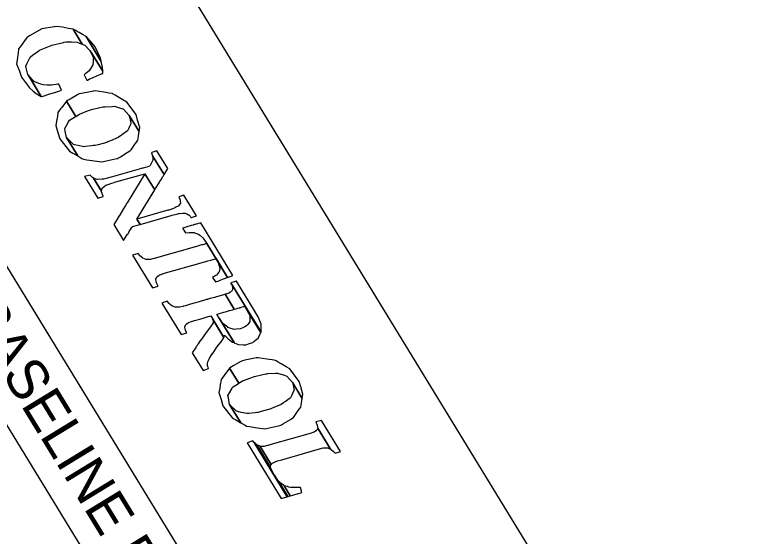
# Model space of a CAD drawing. Extents: x 1761551 to 1780507, y 798394 to 817574.
# Drawn here: x 1775599 to 1777513, y 809485 to 810828 of the extents above; entities that cross this region are included whole.
import ezdxf

# ---------------------------------------------------------------- set-up
doc = ezdxf.new("R2010")
doc.units = 0
for name, color, linetype in [('CTL Sheet Border CELL', 7, 'Continuous'), ('CTL Sheet Text', 7, 'Continuous'), ('Sheet Data Field CELL', 7, 'Continuous')]:
    doc.layers.add(name, color=color, linetype=linetype)

msp = doc.modelspace()

# ---------------------------------------------------------------- linework, layer by layer
at = {"layer": 'CTL Sheet Border CELL'}
for points in [[(1780191.8, 804106.2), (1772031, 817462.6), (1762681.6, 811750.1), (1770842.4, 798393.7)], [(1774358.1, 812175.1), (1777442.6, 807126.8), (1777261.6, 807016.3), (1774177.2, 812064.3)]]:
    msp.add_lwpolyline(points, close=True, dxfattribs=at)
at = {"layer": 'Sheet Data Field CELL'}
for points in [[(1775610.4, 810682.8), (1775616.1, 810667.3), (1775636.5, 810640.1), (1775646.1, 810631.8), (1775653.4, 810625.6), (1775666.6, 810617.7), (1775632.6, 810673.4), (1775632.3, 810674.6), (1775628.9, 810688.4), (1775627.1, 810695.9), (1775630.7, 810703.8), (1775633.6, 810710), (1775637.9, 810719.2), (1775645.3, 810724.7), (1775654.2, 810731.2), (1775654.2, 810731.3), (1775657.5, 810733.7), (1775661.8, 810736.8), (1775692, 810749.2), (1775692, 810749.2), (1775693.9, 810749.9), (1775724.1, 810757.1), (1775725.8, 810757.5), (1775730.7, 810758.6), (1775731.3, 810758.6), (1775744.7, 810758.3), (1775758.7, 810757.9), (1775765.3, 810755.2), (1775772.4, 810752.3), (1775748.8, 810791.1), (1775742.8, 810792.1), (1775737.2, 810793.1), (1775721.7, 810795.9), (1775707, 810798.4), (1775706.4, 810798.3), (1775701.4, 810797.4), (1775699.6, 810797.1), (1775668.3, 810791.7), (1775666.3, 810791.4), (1775638.4, 810775.1), (1775633.9, 810772.4), (1775630.4, 810770.3), (1775623.3, 810760.7), (1775617.5, 810752.6), (1775612.1, 810745.2), (1775608.4, 810740.2), (1775606.9, 810728.8), (1775606.4, 810725.2), (1775605.5, 810718.4), (1775605.5, 810717.8), (1775603.9, 810706.4), (1775603.3, 810701.9)], [(1775755.6, 810787.3), (1775748.8, 810791.1), (1775772.4, 810752.3), (1775778.5, 810749.9), (1775783.7, 810744.6), (1775784.4, 810743.9), (1775792.8, 810735.5), (1775824.8, 810683.1), (1775824.5, 810693.4), (1775821.3, 810708.2), (1775782, 810772.6), (1775773.1, 810777.5), (1775763.9, 810782.7), (1775759.1, 810785.3), (1775758.6, 810785.6)], [(1775793.1, 810759.9), (1775782, 810772.6), (1775821.3, 810708.2), (1775819.5, 810716.6), (1775805.7, 810745.4), (1775805.7, 810745.4)], [(1775777, 810673.7), (1775783.8, 810659.3), (1775785.4, 810660), (1775789.8, 810661.9), (1775790.3, 810662.1), (1775790.3, 810662.1), (1775800.6, 810666.6), (1775811.6, 810671.4), (1775815.5, 810673.1), (1775819.7, 810674.9), (1775823.3, 810676.5), (1775824.9, 810677.2), (1775824.9, 810677.7), (1775824.8, 810683.1), (1775792.8, 810735.5), (1775800.9, 810717), (1775800.8, 810716.6), (1775800.6, 810713.6), (1775800.2, 810706.9), (1775799.7, 810698.9), (1775797.2, 810694.9), (1775790.3, 810683.6), (1775781.3, 810676.9), (1775780.8, 810676.6)], [(1775633.9, 810672), (1775632.6, 810673.4), (1775666.6, 810617.7), (1775667.3, 810617.3), (1775671.5, 810618.6), (1775673.8, 810619.3), (1775673.8, 810619.4), (1775680.9, 810621.6), (1775686.5, 810623.4), (1775694.8, 810626.1), (1775703.8, 810629), (1775703.8, 810629), (1775714.6, 810632.4), (1775718.6, 810633.7), (1775712.2, 810649.7), (1775709.2, 810649.2), (1775704.8, 810648.5), (1775693.1, 810646.6), (1775682.1, 810647), (1775671.9, 810647.4), (1775663.1, 810650.7), (1775652.2, 810654.8), (1775648.6, 810656.1)], [(1775734.3, 810607.3), (1775731.5, 810605.6), (1775755.5, 810566.4), (1775758.3, 810568.1), (1775764.8, 810572.3), (1775785.9, 810580.3), (1775788.7, 810581.3), (1775790.6, 810582.1), (1775790.6, 810582.1), (1775796.1, 810584.2), (1775817.3, 810589.1), (1775825.2, 810590.9), (1775827.4, 810591), (1775830.2, 810591.1), (1775849.7, 810592.2), (1775855.3, 810592.5), (1775863.2, 810590), (1775873.1, 810586.9), (1775874.6, 810586.4), (1775874.6, 810586.4), (1775878.8, 810585.1), (1775893.4, 810568.7), (1775918.7, 810527.2), (1775920.5, 810537.8), (1775914.9, 810557.1), (1775914.9, 810557.1), (1775910.9, 810571.3), (1775886.8, 810603.1), (1775877, 810608.9), (1775864.2, 810616.5), (1775857, 810620.8), (1775851.6, 810624), (1775849.8, 810625.1), (1775840.9, 810626.5), (1775833.8, 810627.6), (1775827.4, 810628.7), (1775805.1, 810632.3), (1775802.4, 810631.8), (1775800.4, 810631.4), (1775792.3, 810629.9), (1775770.6, 810625.8), (1775764.6, 810624.6), (1775762.8, 810623.6), (1775760.4, 810622.2), (1775741.1, 810611.2)], [(1775709.7, 810524.7), (1775714.6, 810508.4), (1775739, 810476.8), (1775747.8, 810471.8), (1775760.7, 810464.4), (1775731.6, 810512), (1775728.4, 810528.6), (1775727.2, 810535), (1775731, 810541.6), (1775737.1, 810552.1), (1775739.5, 810556.3), (1775752, 810564.2), (1775755.5, 810566.4), (1775731.5, 810605.7), (1775728.8, 810602.1), (1775719.3, 810589.3), (1775716.6, 810585.6), (1775709.7, 810576.3), (1775708.1, 810566.2), (1775707.5, 810562.8), (1775706.1, 810553.9), (1775704.3, 810543)], [(1775749.4, 810494.2), (1775731.6, 810512), (1775760.7, 810464.4), (1775771.3, 810458.3), (1775775.4, 810455.9), (1775784.1, 810454.7), (1775797.8, 810452.7), (1775803.3, 810451.9), (1775822.3, 810449.1), (1775826.6, 810450), (1775830, 810450.8), (1775838, 810452.6), (1775860.9, 810457.6), (1775863.9, 810458.2), (1775865.6, 810459.3), (1775870.5, 810462.4), (1775870.5, 810462.4), (1775888, 810473.3), (1775894.6, 810477.4), (1775896.2, 810478.4), (1775897.8, 810480.6), (1775908.6, 810495.8), (1775911.7, 810500.2), (1775915.1, 810505), (1775916.8, 810515.4), (1775917, 810516.9), (1775917.8, 810521.3), (1775918.7, 810527.2), (1775893.4, 810568.7), (1775895.8, 810557.2), (1775897.7, 810548.6), (1775897.1, 810547.5), (1775893.7, 810540.1), (1775890.9, 810534.2), (1775888.4, 810528.8), (1775874.4, 810518.9), (1775872.3, 810517.4), (1775870.8, 810516.3), (1775864.5, 810511.8), (1775845.2, 810503.6), (1775839.9, 810501.3), (1775838, 810500.5), (1775835.4, 810499.4), (1775813, 810493.4), (1775805.2, 810491.3), (1775801.6, 810491), (1775797, 810490.5), (1775780.7, 810488.8), (1775776, 810488.3), (1775761.6, 810491.5), (1775752.5, 810493.5)], [(1775810.7, 810403.7), (1775801.4, 810407.2), (1775822, 810373.4), (1775823.9, 810382), (1775824.4, 810382.4), (1775833.3, 810389.2), (1775835.4, 810390), (1775836, 810390.2), (1775848, 810394.6), (1775854.2, 810396.3), (1775855.1, 810396.6), (1775933.6, 810418.4), (1775958.9, 810376.9), (1775959.8, 810378.5), (1775961.2, 810380.7), (1775968.4, 810392.6), (1775970.9, 810396.6), (1775972.2, 810398.8), (1775972.2, 810398.9), (1775976, 810405.1), (1775976.1, 810405.2), (1775979.8, 810411.3), (1775980.3, 810412.1), (1775981.2, 810413.7), (1775982.9, 810416.3), (1775953.5, 810464.4), (1775953.8, 810458.5), (1775954.1, 810455.1), (1775953.7, 810454), (1775950.9, 810446.5), (1775950.8, 810446.4), (1775947, 810440.1), (1775945.7, 810437.9), (1775941.4, 810436.7), (1775929, 810433.2), (1775926.8, 810432.6), (1775925.2, 810432.1), (1775846.9, 810410.1), (1775846, 810409.8), (1775839.7, 810408.2), (1775827, 810405), (1775826.3, 810404.9), (1775823.8, 810404.7), (1775811.6, 810403.4)], [(1775952.5, 810467), (1775953.5, 810464.4), (1775982.8, 810416.4), (1775983.1, 810416.8), (1775983.5, 810417.4), (1775983.8, 810417.9), (1775983.8, 810417.9), (1775984.5, 810419.1), (1775992.3, 810431.8), (1775964.5, 810477.3), (1775951.5, 810473.1), (1775950.3, 810472.7), (1775950.4, 810472.4), (1775951.4, 810469.9)], [(1775792.5, 810415), (1775778.1, 810411.2), (1775812, 810355.8), (1775826.2, 810359.7), (1775825.7, 810361.2), (1775821.8, 810372.1), (1775822, 810373.4), (1775801.3, 810407.3), (1775799, 810409.4), (1775792.8, 810415.1)], [(1775861.9, 810301.3), (1775853.6, 810287.7), (1775878.6, 810246.7), (1775887.1, 810260.1), (1775887.3, 810260.4), (1775888.7, 810262.6), (1775889.2, 810263.4), (1775892.9, 810269.2), (1775893.2, 810269.7), (1775899.9, 810280.2), (1775901.2, 810282.2), (1775901.8, 810282.4), (1775914.4, 810286), (1775920.5, 810287.8), (1775921.4, 810288.1), (1775913.1, 810301.7), (1775958.9, 810376.9), (1775933.6, 810418.4), (1775887.7, 810343.4), (1775887.1, 810342.5), (1775883.5, 810336.6), (1775876.1, 810324.5), (1775875.8, 810323.9), (1775874.5, 810321.8), (1775867.9, 810311.1), (1775867.6, 810310.6), (1775864, 810304.7), (1775863.5, 810303.9), (1775862.1, 810301.6)], [(1775992.8, 810324.5), (1775913.1, 810301.7), (1775921.4, 810288.1), (1776001, 810311.1), (1776003.3, 810311.7), (1776015.9, 810314.8), (1776020.2, 810315.9), (1776022.6, 810316.4), (1776030, 810316.7), (1776030.1, 810316.8), (1776037.4, 810317), (1776038.8, 810316.4), (1776041.4, 810315.1), (1776046, 810312.9), (1776046.9, 810312.5), (1776049.7, 810309), (1776049.7, 810309), (1776052.2, 810305.8), (1776052.3, 810305.8), (1776053.5, 810306.2), (1776053.5, 810306.2), (1776066.5, 810310.3), (1776033.8, 810363.8), (1776021.1, 810359.1), (1776023.1, 810353.5), (1776023.3, 810353.2), (1776024.1, 810350.9), (1776024.2, 810349.6), (1776024.3, 810348.5), (1776024.8, 810342.4), (1776023.7, 810341.1), (1776023.1, 810340.4), (1776018.9, 810335.2), (1776018.8, 810335), (1776012.9, 810332.2), (1776010.9, 810331.2), (1776007, 810329.3), (1775995, 810325.2)], [(1776039.4, 810281.4), (1776030.2, 810278.8), (1776037.9, 810266.2), (1776047.9, 810267.5), (1776050.6, 810267.5), (1776060.1, 810267.2), (1776064.1, 810265.8), (1776064.1, 810265.9), (1776072, 810263.2), (1776075.2, 810260.2), (1776082.4, 810253.5), (1776085.1, 810249.9), (1776093.1, 810238.9), (1776146.4, 810151.6), (1776160.3, 810156.8), (1776077.7, 810292.1), (1776063.1, 810288), (1776062, 810287.7), (1776061.6, 810287.6), (1776058.9, 810286.9), (1776057.7, 810286.5), (1776052.4, 810285), (1776049.7, 810284.3), (1776041.6, 810282)], [(1775916, 810213.4), (1775901.9, 810208.6), (1775953, 810124.9), (1775967.6, 810128.9), (1775963.6, 810137.3), (1775963.1, 810138.4), (1775961.9, 810145.4), (1775961.6, 810147), (1775963.9, 810152.9), (1775964.1, 810153.4), (1775970.7, 810157.7), (1775971.4, 810158.1), (1775980.5, 810161.2), (1775981, 810161.3), (1776084.1, 810190.6), (1776093.3, 810193.3), (1776095.5, 810193.9), (1776103.5, 810196.2), (1776106.2, 810196.9), (1776111.5, 810198.4), (1776112.7, 810198.8), (1776115.4, 810199.5), (1776115.8, 810199.7), (1776116.8, 810199.9), (1776146.4, 810151.6), (1776146.5, 810151.6), (1776093.1, 810238.9), (1776093.1, 810238.9), (1776092, 810238.6), (1776091.6, 810238.5), (1776089, 810237.7), (1776087.8, 810237.4), (1776082.4, 810235.9), (1776079.7, 810235.1), (1776071.7, 810232.8), (1776069.5, 810232.2), (1776060.3, 810229.6), (1775957.2, 810200.3), (1775956.7, 810200.1), (1775947, 810198), (1775946.2, 810197.8), (1775936.9, 810197.9), (1775936.4, 810197.9), (1775928.5, 810201.2), (1775927.5, 810201.6), (1775920.8, 810207.6), (1775920.5, 810207.9)], [(1776115.8, 810156.4), (1776108, 810151.5), (1776115.2, 810139.8), (1776123.9, 810143.1), (1776126, 810143.9), (1776133.7, 810146.8), (1776136.3, 810147.7), (1776136.3, 810147.8), (1776141.3, 810149.7), (1776142.5, 810150.1), (1776142.5, 810150.1), (1776145, 810151.1), (1776145.4, 810151.2), (1776146.4, 810151.6), (1776116.8, 810199.9), (1776122.7, 810188.4), (1776123.1, 810186.9), (1776126.3, 810176.5), (1776126.1, 810174.6), (1776125, 810166.2), (1776123.1, 810164.1), (1776117.7, 810157.6)], [(1776144.8, 810109.6), (1776140, 810108), (1776163.5, 810069.5), (1776168.5, 810070.9), (1776173, 810072.2), (1776178.2, 810073.6), (1776178.1, 810073.7), (1776180.9, 810074.5), (1776181.4, 810074.6), (1776187.4, 810076.3), (1776188.1, 810076.5), (1776190.6, 810077.2), (1776190.7, 810077.2), (1776191, 810077.3), (1776232.4, 810009.7), (1776232.7, 810010.4), (1776154.8, 810137.9), (1776156.9, 810133.1), (1776157.9, 810130.9), (1776158.1, 810130.5), (1776159.2, 810123.8), (1776159.6, 810121.9), (1776156.5, 810115.2), (1776156.1, 810115), (1776153.7, 810113.7), (1776149.3, 810111.1)], [(1776155.2, 810138), (1776154.9, 810137.9), (1776232.7, 810010.4), (1776232.9, 810010.8), (1776232.6, 810031.2), (1776225, 810049.7), (1776215.2, 810067), (1776169.4, 810141.9), (1776168.7, 810141.7), (1776165.6, 810140.8)], [(1775991.2, 810090.3), (1775977.1, 810085.5), (1776026.6, 810004.6), (1776041.2, 810008.6), (1776038.3, 810015.1), (1776037.9, 810015.9), (1776037.4, 810019), (1776036.7, 810022.9), (1776036.4, 810024.5), (1776038.2, 810028.4), (1776039, 810030.1), (1776039.5, 810031.2), (1776043.1, 810033.5), (1776045.6, 810035.1), (1776046.2, 810035.5), (1776046.4, 810035.6), (1776055.3, 810038.7), (1776055.8, 810038.8), (1776061.6, 810040.5), (1776074.9, 810044.2), (1776074.9, 810044.3), (1776083.8, 810046.8), (1776091.1, 810048.9), (1776096.6, 810050.5), (1776100.9, 810051.7), (1776103, 810052.2), (1776137, 809996.7), (1776137.6, 809997.7), (1776138.7, 810002.9), (1776147.7, 809993.4), (1776159.4, 809985), (1776163, 809983.5), (1776124.5, 810046.4), (1776118.8, 810056.7), (1776119.6, 810056.9), (1776125.3, 810058.6), (1776125.5, 810058.6), (1776136.4, 810061.7), (1776141.3, 810063.1), (1776151.2, 810066), (1776159.8, 810068.4), (1776163.5, 810069.5), (1776140, 810108), (1776136.3, 810106.9), (1776127.7, 810104.4), (1776117.8, 810101.6), (1776112.9, 810100.2), (1776101.9, 810097.1), (1776101.8, 810097), (1776096.1, 810095.4), (1776095.3, 810095.2), (1776094.8, 810095.1), (1776092.6, 810094.4), (1776087, 810092.8), (1776084.2, 810092), (1776080.6, 810091), (1776079.6, 810090.7), (1776077.5, 810090.1), (1776073.2, 810088.9), (1776067.6, 810087.3), (1776060.3, 810085.2), (1776051.4, 810082.6), (1776038.2, 810078.8), (1776032.4, 810077.2), (1776031.9, 810077), (1776022.3, 810074.9), (1776022.1, 810074.9), (1776021.4, 810074.7), (1776017.9, 810074.8), (1776012.8, 810074.8), (1776011.7, 810074.8), (1776009.2, 810075.9), (1776003.7, 810078.1), (1776002.7, 810078.5), (1775999, 810081.8), (1775996, 810084.5), (1775995.7, 810084.8)], [(1776128.5, 810040.9), (1776124.5, 810046.4), (1776163, 809983.5), (1776163.8, 809983.1), (1776165, 809982.6), (1776165, 809982.6), (1776174.3, 809978.5), (1776174.4, 809978.5), (1776187.7, 809977.8), (1776193.6, 809977.5), (1776203.1, 809981), (1776211.3, 809984.1), (1776214.2, 809986.5), (1776214.2, 809986.5), (1776218.1, 809989.7), (1776221.7, 809992.6), (1776225.7, 809995.9), (1776227.1, 809998.9), (1776227.3, 809999.3), (1776227.3, 809999.4), (1776230.5, 810005.8), (1776230.8, 810006.6), (1776232.2, 810009.3), (1776232.2, 810009.3), (1776198.9, 810063.8), (1776199.1, 810063.4), (1776204.2, 810050.2), (1776204.1, 810049), (1776203.5, 810038.4), (1776203.5, 810037.6), (1776201.7, 810035.1), (1776198.4, 810030.7), (1776195.5, 810026.7), (1776191, 810024.5), (1776187.6, 810022.8), (1776179.9, 810019), (1776168.8, 810018.1), (1776163.3, 810017.7), (1776147.4, 810022.7), (1776147.1, 810023), (1776134.4, 810032.7)], [(1776191, 810077.3), (1776198.9, 810063.8), (1776232.2, 810009.3), (1776232.4, 810009.7)], [(1776064.3, 809970.7), (1776055.6, 809957.1), (1776083.3, 809911.6), (1776097.2, 809916.8), (1776096.1, 809920.5), (1776095.9, 809921), (1776094.6, 809925.3), (1776094.9, 809927.7), (1776095, 809928.7), (1776095.5, 809934.5), (1776096.4, 809936.2), (1776096.9, 809937.3), (1776096.9, 809937.3), (1776099.1, 809941.8), (1776100.7, 809945), (1776100.7, 809945), (1776101.1, 809945.7), (1776101.2, 809945.9), (1776106.9, 809954.3), (1776107.2, 809954.8), (1776110.8, 809960), (1776119.2, 809971.7), (1776124.9, 809979.5), (1776129.6, 809985.8), (1776133.2, 809990.6), (1776135.7, 809994.7), (1776137, 809996.7), (1776107.6, 810044.9), (1776110.1, 810036.7), (1776107.7, 810032.4), (1776104.6, 810026.8), (1776099.8, 810020.5), (1776094, 810012.9), (1776085.5, 810001.4), (1776081.8, 809996.3), (1776081.5, 809995.9), (1776075.5, 809987.8), (1776075.4, 809987.7), (1776075, 809987), (1776073.1, 809984.4), (1776070.5, 809980.4), (1776069.9, 809979.5), (1776069, 809978), (1776066.9, 809974.7), (1776066.5, 809974.1), (1776065.6, 809972.8), (1776064.9, 809971.7), (1776064.9, 809971.6)], [(1776154.4, 809919.8), (1776151.5, 809918.2), (1776175.5, 809878.9), (1776178.3, 809880.7), (1776184.9, 809884.8), (1776206, 809892.9), (1776208.7, 809893.9), (1776210.6, 809894.6), (1776210.6, 809894.6), (1776216.1, 809896.7), (1776237.3, 809901.6), (1776245.3, 809903.4), (1776247.4, 809903.5), (1776250.3, 809903.7), (1776269.7, 809904.8), (1776275.3, 809905.1), (1776283.2, 809902.6), (1776293.1, 809899.4), (1776294.6, 809898.9), (1776294.6, 809899), (1776298.8, 809897.6), (1776313.4, 809881.2), (1776338.8, 809839.8), (1776340.5, 809850.4), (1776335, 809869.6), (1776335, 809869.6), (1776330.9, 809883.8), (1776306.8, 809915.7), (1776297.1, 809921.5), (1776284.2, 809929.1), (1776277, 809933.3), (1776271.7, 809936.5), (1776269.8, 809937.6), (1776260.9, 809939), (1776253.8, 809940.2), (1776247.4, 809941.2), (1776225.1, 809944.8), (1776222.5, 809944.4), (1776220.5, 809944), (1776212.4, 809942.4), (1776190.7, 809938.3), (1776184.6, 809937.1), (1776182.9, 809936.1), (1776180.4, 809934.7), (1776161.1, 809923.7)], [(1776129.7, 809837.3), (1776134.6, 809820.9), (1776159, 809789.3), (1776167.8, 809784.3), (1776180.8, 809776.9), (1776151.7, 809824.6), (1776148.5, 809841.1), (1776147.2, 809847.5), (1776151, 809854.1), (1776157.1, 809864.7), (1776159.5, 809868.8), (1776172, 809876.7), (1776175.5, 809878.9), (1776151.5, 809918.2), (1776148.9, 809914.6), (1776139.4, 809901.8), (1776136.6, 809898.1), (1776129.8, 809888.9), (1776128.1, 809878.7), (1776127.5, 809875.3), (1776126.1, 809866.4), (1776124.3, 809855.5)], [(1776169.5, 809806.7), (1776151.7, 809824.6), (1776180.8, 809776.9), (1776191.4, 809770.8), (1776195.5, 809768.5), (1776204.1, 809767.2), (1776217.9, 809765.2), (1776223.3, 809764.4), (1776242.4, 809761.6), (1776246.6, 809762.6), (1776250, 809763.3), (1776258, 809765.1), (1776281, 809770.1), (1776283.9, 809770.8), (1776285.6, 809771.9), (1776290.5, 809774.9), (1776290.5, 809774.9), (1776308.1, 809785.8), (1776314.6, 809789.9), (1776316.2, 809790.9), (1776317.8, 809793.2), (1776328.6, 809808.4), (1776331.7, 809812.8), (1776335.1, 809817.6), (1776336.8, 809827.9), (1776337.1, 809829.4), (1776337.8, 809833.8), (1776338.8, 809839.8), (1776313.4, 809881.3), (1776315.9, 809869.7), (1776317.7, 809861.2), (1776317.2, 809860.1), (1776313.7, 809852.7), (1776310.9, 809846.7), (1776308.4, 809841.4), (1776294.4, 809831.4), (1776292.4, 809830), (1776290.8, 809828.8), (1776284.5, 809824.4), (1776265.3, 809816.2), (1776259.9, 809813.9), (1776258.1, 809813.1), (1776255.4, 809811.9), (1776233.1, 809806), (1776225.2, 809803.9), (1776221.6, 809803.5), (1776217.1, 809803), (1776200.8, 809801.4), (1776196.1, 809800.9), (1776181.6, 809804), (1776172.5, 809806)], [(1776378.3, 809765.2), (1776378.6, 809763.5), (1776411.6, 809709.3), (1776412.6, 809708.9), (1776419.3, 809702.9), (1776419.7, 809702.6), (1776423.3, 809698.5), (1776437.4, 809703.3), (1776388.4, 809783.4), (1776373.9, 809779.4), (1776376.7, 809772.9), (1776377.1, 809772.1)], [(1776237.3, 809716.3), (1776230.7, 809716.4), (1776259, 809670), (1776263.1, 809674), (1776265.6, 809675), (1776268.2, 809676.1), (1776268.2, 809676.1), (1776273.7, 809678.3), (1776275.2, 809678.7), (1776275.2, 809678.8), (1776286, 809681.9), (1776383, 809710.3), (1776383.5, 809710.4), (1776392.8, 809712.5), (1776394, 809712.7), (1776402.5, 809712.6), (1776402.5, 809712.6), (1776403.7, 809712.6), (1776411.6, 809709.3), (1776378.5, 809763.5), (1776376, 809757.9), (1776375.5, 809756.8), (1776369.2, 809753.2), (1776368.3, 809752.7), (1776359.5, 809749.7), (1776359, 809749.5), (1776261.7, 809721.7), (1776250.9, 809718.6), (1776249.3, 809718.3), (1776243.3, 809716.9), (1776240.4, 809716.3)], [(1776211.1, 809730.5), (1776197, 809725.7), (1776284.6, 809582.2), (1776299.1, 809586.3), (1776300.1, 809586.6), (1776214.7, 809726.3)], [(1776215.2, 809725.9), (1776214.7, 809726.4), (1776300.1, 809586.6), (1776300.3, 809586.7), (1776266.1, 809642.6), (1776260.7, 809654.2), (1776257, 809662.2), (1776257, 809662.3), (1776221.7, 809720.1), (1776221.6, 809720.2), (1776219, 809722.5)], [(1776228.6, 809717.3), (1776221.7, 809720.1), (1776257, 809662.3), (1776258, 809669), (1776258.5, 809669.5), (1776259, 809670), (1776230.6, 809716.4), (1776229.7, 809716.8)], [(1776278.3, 809625.5), (1776266.1, 809642.6), (1776300.3, 809586.7), (1776301.7, 809587.1)], [(1776280.5, 809623.7), (1776278.3, 809625.4), (1776301.7, 809587.1), (1776302.8, 809587.3), (1776302.8, 809587.4), (1776307.2, 809588.6), (1776307.9, 809588.8), (1776291.8, 809615.1), (1776290.3, 809616.2), (1776280.7, 809623.6)], [(1776292.7, 809614.8), (1776291.8, 809615), (1776307.9, 809588.8), (1776308.5, 809589), (1776314.1, 809590.6), (1776316.8, 809591.3), (1776319.5, 809592.2), (1776325.3, 809593.8), (1776326.9, 809594.2), (1776337.7, 809597.3), (1776333.9, 809610.3), (1776329.7, 809610.4), (1776316.9, 809610.5), (1776315.1, 809610.5), (1776308.3, 809610.6), (1776304.4, 809611.6), (1776300.6, 809612.7)]]:
    msp.add_lwpolyline(points, close=True, dxfattribs=at)

# ---------------------------------------------------------------- texts
at = {"layer": 'CTL Sheet Text'}
for s, height, p in [('    POINT          DESC.           NORTH             EAST          ELEVATION           L STATION       OFFSET', 50, (1774050.5, 811827)), ('BASELINE DATA', 104.346, (1775466.9, 810061.6))]:
    msp.add_text(s, height=height, rotation=301.4249, dxfattribs=at).set_placement(p)

doc.saveas('drawing.dxf')
